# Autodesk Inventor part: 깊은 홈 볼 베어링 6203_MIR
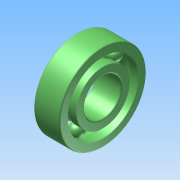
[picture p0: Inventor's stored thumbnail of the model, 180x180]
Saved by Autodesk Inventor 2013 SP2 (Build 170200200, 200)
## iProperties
Created: 2026-07
Part Number: 깊은 홈 볼 베어링 6203_MIR
Material: Generic
Document SubType Name: Modeling
Designer: aa
Density: 1 g/cm^3
Author: aa
변환 표준: STEP AP214IS
전처리기: Build: 200, Release: 2013 SP2 Update 6 - Date: Thu 07/17/2014
전송 단위: 밀리미터
불확실성: 0.01
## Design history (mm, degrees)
derived "깊은 홈 볼 베어링 6203.ipt"
feature "Solid1::깊은 홈 볼 베어링 6203.ipt"
feature "Solid1_1::깊은 홈 볼 베어링 6203.ipt"
feature "Solid1_2::깊은 홈 볼 베어링 6203.ipt"
feature "Solid1_3::깊은 홈 볼 베어링 6203.ipt"
feature "Solid1_4::깊은 홈 볼 베어링 6203.ipt"
feature "Solid1_5::깊은 홈 볼 베어링 6203.ipt"
feature "Solid1_6::깊은 홈 볼 베어링 6203.ipt"
feature "Solid1_7::깊은 홈 볼 베어링 6203.ipt"
feature "Solid1_8::깊은 홈 볼 베어링 6203.ipt"
tag "피쳐 태그1"
node "솔리드1"
node "솔리드2"
node "솔리드3"
node "솔리드4"
node "솔리드5"
node "솔리드6"
node "솔리드7"
node "솔리드8"
node "솔리드9"
